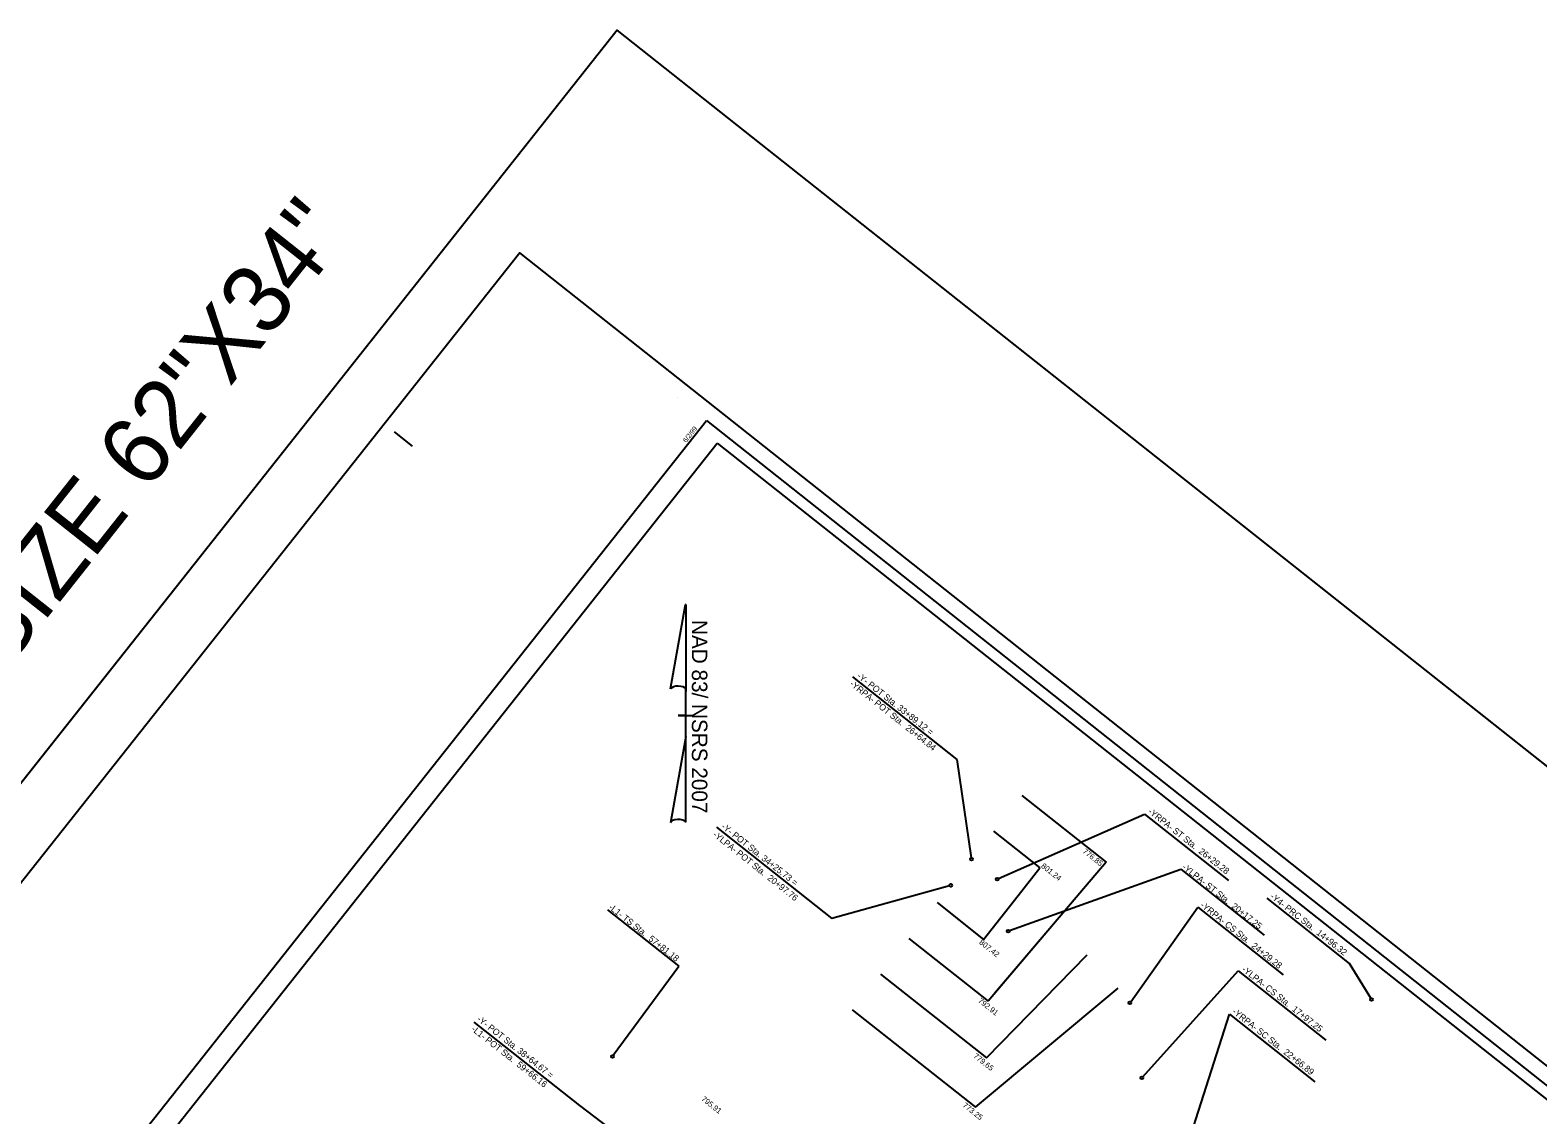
# Model space of a CAD drawing. Extents: x 1780292 to 1784627, y 810983 to 814799.
# Drawn here: x 1781173 to 1782828, y 813608 to 814799 of the extents above; entities that cross this region are included whole.
import ezdxf

# ---------------------------------------------------------------- set-up
doc = ezdxf.new("R2010")
doc.units = 0
for name, color, linetype in [('Prop Horizontal Alignment Station Label', 7, 'Continuous'), ('Prop North Arrow NAD83 for Plan Sheets CELL', 7, 'Continuous'), ('Prop Shear Point Element on Plans', 7, 'Continuous'), ('Prop Shear Point Label', 7, 'Continuous'), ('Sheet Clip Boundary CELL', 7, 'Continuous'), ('Sheet Cutting Line CELL', 7, 'Continuous'), ('Sheet Detail CELL', 7, 'Continuous'), ('Sheet Plot Border Inside CELL', 7, 'Continuous'), ('Sheet Plot Border Outside CELL', 7, 'Continuous')]:
    doc.layers.add(name, color=color, linetype=linetype)

msp = doc.modelspace()

# ---------------------------------------------------------------- linework, layer by layer
at = {"layer": 'Prop Horizontal Alignment Station Label'}
for p, q in [((1782190.7, 813998.1), (1782076.1, 814088.9)), ((1782206.3, 813890), (1782190.7, 813998.1)), ((1782236, 813867.3), (1782396.3, 813938.1)), ((1782396.3, 813938.1), (1782488.6, 813865)), ((1781926.5, 813923.7), (1782053.2, 813823.3)), ((1782248.2, 813810.1), (1782436.1, 813877.7)), ((1782436.1, 813877.7), (1782527.7, 813805.2)), ((1782182.4, 813859.4), (1782053.2, 813823.3)), ((1782381.2, 813731.9), (1782455, 813835.7)), ((1782455, 813835.7), (1782548.7, 813761.5)), ((1782621.6, 813774), (1782530.9, 813845.9)), ((1781806.8, 813832.9), (1781885.1, 813771)), ((1781813.2, 813673.2), (1781885.1, 813771)), ((1782645, 813735.9), (1782621.6, 813774)), ((1782394.4, 813649.7), (1782499.1, 813766)), ((1782499.1, 813766), (1782595.5, 813689.7)), ((1781660.3, 813709.6), (1781776.1, 813618)), ((1782447.4, 813585.4), (1782489.7, 813718.3)), ((1782489.7, 813718.3), (1782583.3, 813644.2)), ((1781776.1, 813618), (1781910.2, 813516.6))]:
    msp.add_line(p, q, dxfattribs=at)
for centre in [(1782206.5, 813888.5), (1782234.6, 813866.7), (1782183.8, 813859.8), (1782246.8, 813809.6), (1782645.7, 813734.6), (1782380.4, 813730.7), (1781812.4, 813672), (1782393.4, 813648.6)]:
    msp.add_circle(centre, 1.5, dxfattribs=at)
at = {"layer": 'Prop North Arrow NAD83 for Plan Sheets CELL'}
for p, q in [((1781876.2, 814075.6), (1781892.6, 814168.3)), ((1781892.7, 814168.3), (1781892.6, 814168.3)), ((1781892.7, 814168.3), (1781892.6, 814168.3)), ((1781892.7, 814168.3), (1781892.7, 814072.7)), ((1781892.7, 814023.1), (1781892.7, 814075.5)), ((1781892.7, 814072.7), (1781892.7, 814075.4)), ((1781884.7, 814046.3), (1781884.6, 814046.3)), ((1781891.8, 814046.3), (1781884.7, 814046.3)), ((1781884.8, 814046.3), (1781900.8, 814046.3)), ((1781892.7, 814023.1), (1781876, 813928.6)), ((1781892.8, 813929), (1781892.7, 814023.1))]:
    msp.add_line(p, q, dxfattribs=at)
for centre, start_param, end_param in [((1781884.5, 814074.6), 0.216388, 2.908219), ((1781884.5, 813928.2), 0.201328, 3.141593)]:
    msp.add_ellipse(centre, major_axis=(8.46, -0.06), ratio=0.461098, start_param=start_param, end_param=end_param, dxfattribs=at)
at = {"layer": 'Prop Shear Point Element on Plans'}
for p, q in [((1782261.9, 813958.4), (1782354.3, 813885.3)), ((1782230.8, 813919.2), (1782281.6, 813879)), ((1782354.3, 813885.3), (1782296.4, 813817.1)), ((1782257.7, 813848.7), (1782281.6, 813879)), ((1782168.8, 813840.8), (1782219.7, 813800.5)), ((1782219.7, 813800.5), (1782257.7, 813848.7)), ((1782137.7, 813801.6), (1782224.8, 813732.7)), ((1782296.4, 813817.1), (1782224.8, 813732.7)), ((1782296.4, 813817.1), (1782231.7, 813740.9)), ((1782223, 813670.3), (1782333.5, 813783.6)), ((1782106.7, 813762.4), (1782223, 813670.3)), ((1782210.7, 813616.3), (1782367.5, 813747)), ((1782075.6, 813723.2), (1782210.7, 813616.3))]:
    msp.add_line(p, q, dxfattribs=at)
at = {"layer": 'Sheet Clip Boundary CELL'}
msp.add_lwpolyline([(1781927.1, 814345.3), (1784094.1, 812630.7), (1783998.7, 812510.2), (1784155.1, 812386.4), (1783319, 811330.3), (1782987.6, 811592.6), (1782917.5, 811504.1), (1780926, 813080.8)], close=True, dxfattribs=at)
at = {"layer": 'Sheet Cutting Line CELL'}
for p, q in [((1781817.4, 814798.8), (1780451.8, 813073.9)), ((1784458, 812708.2), (1781817.4, 814798.8))]:
    msp.add_line(p, q, dxfattribs=at)
at = {"layer": 'Sheet Detail CELL'}
for p, q in [((1781883.7, 814395.5), (1781883.7, 814395.5)), ((1781572.7, 814357.6), (1781592.3, 814342.1)), ((1782038.6, 814272.9), (1782038.6, 814272.9))]:
    msp.add_line(p, q, dxfattribs=at)
msp.add_lwpolyline([(1781915.6, 814370.3), (1784267.7, 812508.1), (1783243.5, 811214.5), (1780891.4, 813076.6)], close=True, dxfattribs=at)
at = {"layer": 'Sheet Plot Border Inside CELL'}
msp.add_lwpolyline([(1784297.9, 812505.9), (1781710.6, 814554.3), (1780665.3, 813234), (1783252.6, 811185.6)], close=True, dxfattribs=at)
at = {"layer": 'Sheet Plot Border Outside CELL'}
msp.add_lwpolyline([(1784458, 812708.2), (1781817.4, 814798.8), (1780451.8, 813073.9), (1783092.4, 810983.3)], close=True, dxfattribs=at)

# ---------------------------------------------------------------- texts
at = {"layer": 'Prop Horizontal Alignment Station Label'}
for s, rotation, p in [('-YRPA- POT Sta.  26+64.84', 321.5287, (1782072.2, 814080)), ('-Y- POT Sta. 33+89.12 =', 321.6309, (1782080.2, 814088.3)), ('-YRPA- ST Sta.  26+29.28', 321.6871, (1782399.7, 813939.7)), ('-YLPA- POT Sta.  20+97.76', 321.4277, (1781922, 813914.3)), ('-Y- POT Sta. 34+25.73 =', 321.6309, (1781931.2, 813923.1)), ('-YLPA- ST Sta.  20+17.25', 321.469, (1782437.1, 813878.7)), ('-L1- TS Sta.  57+81.18', 321.6264, (1781807.6, 813834.5)), ('-YRPA- CS Sta.  24+29.28', 321.4947, (1782457, 813836.9)), ('-Y4- PRC Sta.  14+96.32', 321.8079, (1782533.7, 813846.4)), ('-YLPA- CS Sta.  17+97.25', 321.612, (1782502.6, 813766.3)), ('-YRPA- SC Sta.  22+66.89', 321.5353, (1782492.1, 813720)), ('-L1- POT Sta.  59+66.16', 321.7606, (1781656.9, 813700.7)), ('-Y- POT Sta. 38+64.67 =', 321.6309, (1781663, 813711.7))]:
    msp.add_text(s, height=7, rotation=rotation, dxfattribs=at).set_placement(p)
at = {"layer": 'Prop North Arrow NAD83 for Plan Sheets CELL'}
msp.add_text('NAD 83/ NSRS 2007', height=17, rotation=270, dxfattribs=at).set_placement((1781899.5, 814151.1))
at = {"layer": 'Prop Shear Point Element on Plans'}
msp.add_text('795.91', height=6, rotation=321.6309, dxfattribs=at).set_placement((1781909.4, 813624.3))
at = {"layer": 'Prop Shear Point Label'}
for s, p in [('776.85', (1782327.9, 813896.1)), ('801.24', (1782282.3, 813880)), ('807.42', (1782214.3, 813796.2)), ('792.91', (1782213.1, 813732.1)), ('779.65', (1782208, 813671.4)), ('773.25', (1782196.1, 813617.3))]:
    msp.add_text(s, height=6, rotation=321.6309, dxfattribs=at).set_placement(p)
at = {"layer": 'Sheet Detail CELL'}
for s, height, p in [('TO PLOT FULL SIZE 62"X34"', 75, (1780692, 813521.9)), ('6/2/99', 5.25, (1781893.2, 814345.4))]:
    msp.add_text(s, height=height, rotation=51.6309, dxfattribs=at).set_placement(p)

doc.saveas('drawing.dxf')
